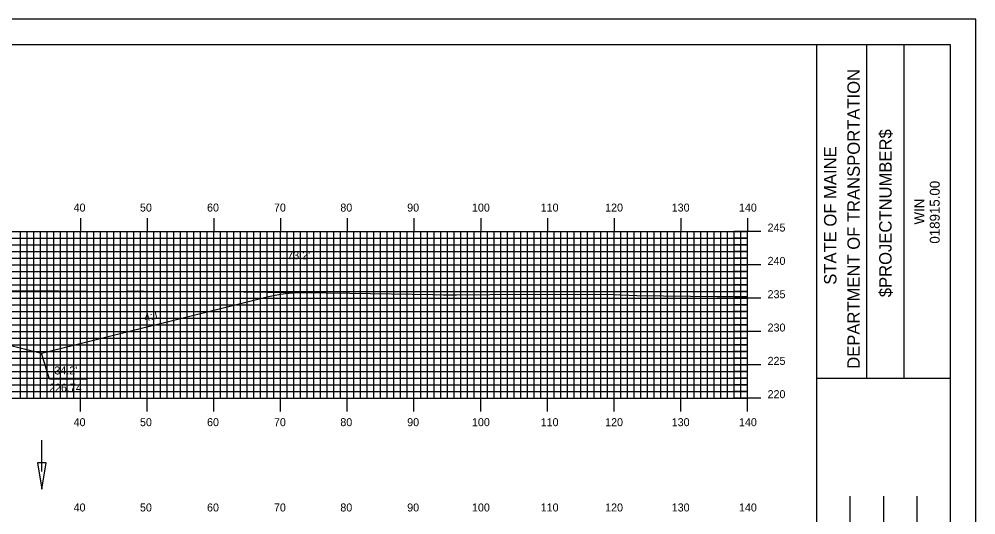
# Model space of a CAD drawing. Extents: x 1802716 to 1803060, y 442591 to 442811.
# Drawn here: x 1802912.9 to 1803056.3, y 442736.2 to 442810.5 of the extents above; entities that cross this region are included whole.
import ezdxf

# ---------------------------------------------------------------- set-up
doc = ezdxf.new("R2010")
doc.units = 0
for name, color, linetype in [('ANNOTATION', 7, 'Continuous'), ('BORDER', 7, 'Continuous'), ('D_Drainage_Ditch_Line', 7, 'Continuous'), ('D_Roadway_Centerline', 7, 'Continuous'), ('D_Roadway_SlopeLines', 7, 'Continuous'), ('D_Text_Standard', 7, 'Continuous'), ('H_V ANNOTATION', 7, 'Continuous'), ('MAJOR', 7, 'Continuous'), ('MINOR', 7, 'Continuous'), ('PLOT BOUNDARY', 7, 'Continuous'), ('S_Roadway_Centerline', 7, 'Continuous')]:
    doc.layers.add(name, color=color, linetype=linetype)

msp = doc.modelspace()

# ---------------------------------------------------------------- linework, layer by layer
at = {"layer": 'ANNOTATION'}
msp.add_lwpolyline([(1802923.17, 442756.5), (1802917.48, 442756.5), (1802916.29, 442760.41)], dxfattribs=at)
at = {"layer": 'BORDER'}
for p, q in [((1803032.51, 442596.67), (1803032.51, 442806.67)), ((1803039.97, 442756.66), (1803039.97, 442806.66)), ((1803045.56, 442756.66), (1803045.56, 442806.66)), ((1803032.52, 442756.65), (1803052.51, 442756.65)), ((1803037.51, 442721.67), (1803037.51, 442738.97)), ((1803042.51, 442721.67), (1803042.51, 442738.97)), ((1803047.51, 442721.67), (1803047.51, 442738.97))]:
    msp.add_line(p, q, dxfattribs=at)
msp.add_lwpolyline([(1802732.51, 442596.67), (1803052.51, 442596.67), (1803052.51, 442806.67), (1802732.51, 442806.67)], close=True, dxfattribs=at)
at = {"layer": 'D_Drainage_Ditch_Line'}
msp.add_line((1802916.32, 442742.65), (1802916.32, 442747.35), dxfattribs=at)
msp.add_lwpolyline([(1802916.97, 442743.96), (1802915.66, 442743.96), (1802916.32, 442740.03)], close=True, dxfattribs=at)
at = {"layer": 'D_Roadway_Centerline'}
msp.add_lwpolyline([(1802805.64, 442770.35), (1802806.89, 442770.32), (1802808.14, 442770.2), (1802809.39, 442770.01), (1802810.64, 442769.74), (1802847.94, 442760.41), (1802851.94, 442761.41), (1802862.11, 442763.95), (1802870.11, 442764.27), (1802882.11, 442764.51), (1802894.11, 442764.27), (1802902.11, 442763.95), (1802912.29, 442761.41), (1802916.29, 442760.41), (1802950.28, 442768.91), (1802951.53, 442769.18), (1802952.78, 442769.37), (1802954.03, 442769.48), (1802955.28, 442769.51)], dxfattribs=at)
at = {"layer": 'D_Roadway_SlopeLines'}
for points in [[(1802916.29, 442760.41), (1802950.28, 442768.91), (1802951.53, 442769.18), (1802952.78, 442769.37), (1802954.03, 442769.48), (1802955.28, 442769.51)], [(1802902.11, 442763.95), (1802916.29, 442760.41)]]:
    msp.add_lwpolyline(points, dxfattribs=at)
at = {"layer": 'MAJOR'}
for p, q in [((1802922.11, 442780.67), (1802922.11, 442778.67)), ((1802932.11, 442780.67), (1802932.11, 442778.67)), ((1802942.11, 442780.67), (1802942.11, 442778.67)), ((1802952.11, 442780.67), (1802952.11, 442778.67)), ((1802962.11, 442780.67), (1802962.11, 442778.67)), ((1802972.11, 442780.67), (1802972.11, 442778.67)), ((1802982.11, 442780.67), (1802982.11, 442778.67)), ((1802992.11, 442780.67), (1802992.11, 442778.67)), ((1803002.11, 442780.67), (1803002.11, 442778.67)), ((1803012.11, 442780.67), (1803012.11, 442778.67)), ((1803022.11, 442780.67), (1803022.11, 442778.67)), ((1802742.11, 442778.67), (1803022.11, 442778.67)), ((1802742.11, 442778.67), (1803022.11, 442778.67)), ((1802922.11, 442753.67), (1802922.11, 442778.67)), ((1802932.11, 442753.67), (1802932.11, 442778.67)), ((1802942.11, 442753.67), (1802942.11, 442778.67)), ((1802952.11, 442753.67), (1802952.11, 442778.67)), ((1802962.11, 442753.67), (1802962.11, 442778.67)), ((1802972.11, 442753.67), (1802972.11, 442778.67)), ((1802982.11, 442753.67), (1802982.11, 442778.67)), ((1802992.11, 442753.67), (1802992.11, 442778.67)), ((1803002.11, 442753.67), (1803002.11, 442778.67)), ((1803012.11, 442753.67), (1803012.11, 442778.67)), ((1803024.12, 442778.67), (1803020.11, 442778.67)), ((1803022.11, 442753.67), (1803022.11, 442778.67)), ((1803022.11, 442753.67), (1803022.11, 442778.67)), ((1802742.11, 442773.67), (1803022.11, 442773.67)), ((1803024.12, 442773.67), (1803020.11, 442773.67)), ((1802742.11, 442768.67), (1803022.11, 442768.67)), ((1803024.12, 442768.67), (1803020.11, 442768.67)), ((1802742.11, 442763.67), (1803022.11, 442763.67)), ((1803024.12, 442763.67), (1803020.11, 442763.67)), ((1802742.11, 442758.67), (1803022.11, 442758.67)), ((1803024.12, 442758.67), (1803020.11, 442758.67)), ((1802742.11, 442753.67), (1803022.11, 442753.67)), ((1802742.11, 442753.67), (1803022.11, 442753.67)), ((1802922.11, 442751.66), (1802922.11, 442753.67)), ((1802932.11, 442751.66), (1802932.11, 442753.67)), ((1802942.11, 442751.66), (1802942.11, 442753.67)), ((1802952.11, 442751.66), (1802952.11, 442753.67)), ((1802962.11, 442751.66), (1802962.11, 442753.67)), ((1802972.11, 442751.66), (1802972.11, 442753.67)), ((1802982.11, 442751.66), (1802982.11, 442753.67)), ((1802992.11, 442751.66), (1802992.11, 442753.67)), ((1803002.11, 442751.66), (1803002.11, 442753.67)), ((1803012.11, 442751.66), (1803012.11, 442753.67)), ((1803024.12, 442753.67), (1803020.11, 442753.67)), ((1803022.11, 442751.66), (1803022.11, 442753.67))]:
    msp.add_line(p, q, dxfattribs=at)
at = {"layer": 'MINOR'}
for p, q in [((1802913.11, 442753.67), (1802913.11, 442778.67)), ((1802914.11, 442753.67), (1802914.11, 442778.67)), ((1802915.11, 442753.67), (1802915.11, 442778.67)), ((1802916.11, 442753.67), (1802916.11, 442778.67)), ((1802917.11, 442753.67), (1802917.11, 442778.67)), ((1802918.11, 442753.67), (1802918.11, 442778.67)), ((1802919.11, 442753.67), (1802919.11, 442778.67)), ((1802920.11, 442753.67), (1802920.11, 442778.67)), ((1802921.11, 442753.67), (1802921.11, 442778.67)), ((1802923.11, 442753.67), (1802923.11, 442778.67)), ((1802924.11, 442753.67), (1802924.11, 442778.67)), ((1802925.11, 442753.67), (1802925.11, 442778.67)), ((1802926.11, 442753.67), (1802926.11, 442778.67)), ((1802927.11, 442753.67), (1802927.11, 442778.67)), ((1802928.11, 442753.67), (1802928.11, 442778.67)), ((1802929.11, 442753.67), (1802929.11, 442778.67)), ((1802930.11, 442753.67), (1802930.11, 442778.67)), ((1802931.11, 442753.67), (1802931.11, 442778.67)), ((1802933.11, 442753.67), (1802933.11, 442778.67)), ((1802934.11, 442753.67), (1802934.11, 442778.67)), ((1802935.11, 442753.67), (1802935.11, 442778.67)), ((1802936.11, 442753.67), (1802936.11, 442778.67)), ((1802937.11, 442753.67), (1802937.11, 442778.67)), ((1802938.11, 442753.67), (1802938.11, 442778.67)), ((1802939.11, 442753.67), (1802939.11, 442778.67)), ((1802940.11, 442753.67), (1802940.11, 442778.67)), ((1802941.11, 442753.67), (1802941.11, 442778.67)), ((1802943.11, 442753.67), (1802943.11, 442778.67)), ((1802944.11, 442753.67), (1802944.11, 442778.67)), ((1802945.11, 442753.67), (1802945.11, 442778.67)), ((1802946.11, 442753.67), (1802946.11, 442778.67)), ((1802947.11, 442753.67), (1802947.11, 442778.67)), ((1802948.11, 442753.67), (1802948.11, 442778.67)), ((1802949.11, 442753.67), (1802949.11, 442778.67)), ((1802950.11, 442753.67), (1802950.11, 442778.67)), ((1802951.11, 442753.67), (1802951.11, 442778.67)), ((1802953.11, 442753.67), (1802953.11, 442778.67)), ((1802954.11, 442753.67), (1802954.11, 442778.67)), ((1802955.11, 442753.67), (1802955.11, 442778.67)), ((1802956.11, 442753.67), (1802956.11, 442778.67)), ((1802957.11, 442753.67), (1802957.11, 442778.67)), ((1802958.11, 442753.67), (1802958.11, 442778.67)), ((1802959.11, 442753.67), (1802959.11, 442778.67)), ((1802960.11, 442753.67), (1802960.11, 442778.67)), ((1802961.11, 442753.67), (1802961.11, 442778.67)), ((1802963.11, 442753.67), (1802963.11, 442778.67)), ((1802964.11, 442753.67), (1802964.11, 442778.67)), ((1802965.11, 442753.67), (1802965.11, 442778.67)), ((1802966.11, 442753.67), (1802966.11, 442778.67)), ((1802967.11, 442753.67), (1802967.11, 442778.67)), ((1802968.11, 442753.67), (1802968.11, 442778.67)), ((1802969.11, 442753.67), (1802969.11, 442778.67)), ((1802970.11, 442753.67), (1802970.11, 442778.67)), ((1802971.11, 442753.67), (1802971.11, 442778.67)), ((1802973.11, 442753.67), (1802973.11, 442778.67)), ((1802974.11, 442753.67), (1802974.11, 442778.67)), ((1802975.11, 442753.67), (1802975.11, 442778.67)), ((1802976.11, 442753.67), (1802976.11, 442778.67)), ((1802977.11, 442753.67), (1802977.11, 442778.67)), ((1802978.11, 442753.67), (1802978.11, 442778.67)), ((1802979.11, 442753.67), (1802979.11, 442778.67)), ((1802980.11, 442753.67), (1802980.11, 442778.67)), ((1802981.11, 442753.67), (1802981.11, 442778.67)), ((1802983.11, 442753.67), (1802983.11, 442778.67)), ((1802984.11, 442753.67), (1802984.11, 442778.67)), ((1802985.11, 442753.67), (1802985.11, 442778.67)), ((1802986.11, 442753.67), (1802986.11, 442778.67)), ((1802987.11, 442753.67), (1802987.11, 442778.67)), ((1802988.11, 442753.67), (1802988.11, 442778.67)), ((1802989.11, 442753.67), (1802989.11, 442778.67)), ((1802990.11, 442753.67), (1802990.11, 442778.67)), ((1802991.11, 442753.67), (1802991.11, 442778.67)), ((1802993.11, 442753.67), (1802993.11, 442778.67)), ((1802994.11, 442753.67), (1802994.11, 442778.67)), ((1802995.11, 442753.67), (1802995.11, 442778.67)), ((1802996.11, 442753.67), (1802996.11, 442778.67)), ((1802997.11, 442753.67), (1802997.11, 442778.67)), ((1802998.11, 442753.67), (1802998.11, 442778.67)), ((1802999.11, 442753.67), (1802999.11, 442778.67)), ((1803000.11, 442753.67), (1803000.11, 442778.67)), ((1803001.11, 442753.67), (1803001.11, 442778.67)), ((1803003.11, 442753.67), (1803003.11, 442778.67)), ((1803004.11, 442753.67), (1803004.11, 442778.67)), ((1803005.11, 442753.67), (1803005.11, 442778.67)), ((1803006.11, 442753.67), (1803006.11, 442778.67)), ((1803007.11, 442753.67), (1803007.11, 442778.67)), ((1803008.11, 442753.67), (1803008.11, 442778.67)), ((1803009.11, 442753.67), (1803009.11, 442778.67)), ((1803010.11, 442753.67), (1803010.11, 442778.67)), ((1803011.11, 442753.67), (1803011.11, 442778.67)), ((1803013.11, 442753.67), (1803013.11, 442778.67)), ((1803014.11, 442753.67), (1803014.11, 442778.67)), ((1803015.11, 442753.67), (1803015.11, 442778.67)), ((1803016.11, 442753.67), (1803016.11, 442778.67)), ((1803017.11, 442753.67), (1803017.11, 442778.67)), ((1803018.11, 442753.67), (1803018.11, 442778.67)), ((1803019.11, 442753.67), (1803019.11, 442778.67)), ((1803020.11, 442753.67), (1803020.11, 442778.67)), ((1803021.11, 442753.67), (1803021.11, 442778.67)), ((1802742.11, 442777.67), (1803022.11, 442777.67)), ((1803022.11, 442777.67), (1803020.11, 442777.67)), ((1802742.11, 442776.67), (1803022.11, 442776.67)), ((1802742.11, 442775.67), (1803022.11, 442775.67)), ((1803022.11, 442776.67), (1803020.11, 442776.67)), ((1803022.11, 442775.67), (1803020.11, 442775.67)), ((1802742.11, 442774.67), (1803022.11, 442774.67)), ((1803022.11, 442774.67), (1803020.11, 442774.67)), ((1802742.11, 442772.67), (1803022.11, 442772.67)), ((1802742.11, 442771.67), (1803022.11, 442771.67)), ((1803022.11, 442772.67), (1803020.11, 442772.67)), ((1803022.11, 442771.67), (1803020.11, 442771.67)), ((1802742.11, 442770.67), (1803022.11, 442770.67)), ((1803022.11, 442770.67), (1803020.11, 442770.67)), ((1802742.11, 442769.67), (1803022.11, 442769.67)), ((1803022.11, 442769.67), (1803020.11, 442769.67)), ((1802742.11, 442767.67), (1803022.11, 442767.67)), ((1803022.11, 442767.67), (1803020.11, 442767.67)), ((1802742.11, 442766.67), (1803022.11, 442766.67)), ((1802742.11, 442765.67), (1803022.11, 442765.67)), ((1803022.11, 442766.67), (1803020.11, 442766.67)), ((1803022.11, 442765.67), (1803020.11, 442765.67)), ((1802742.11, 442764.67), (1803022.11, 442764.67)), ((1803022.11, 442764.67), (1803020.11, 442764.67)), ((1802742.11, 442762.67), (1803022.11, 442762.67)), ((1802742.11, 442761.67), (1803022.11, 442761.67)), ((1803022.11, 442762.67), (1803020.11, 442762.67)), ((1803022.11, 442761.67), (1803020.11, 442761.67)), ((1802742.11, 442760.67), (1803022.11, 442760.67)), ((1803022.11, 442760.67), (1803020.11, 442760.67)), ((1802742.11, 442759.67), (1803022.11, 442759.67)), ((1803022.11, 442759.67), (1803020.11, 442759.67)), ((1802742.11, 442757.67), (1803022.11, 442757.67)), ((1803022.11, 442757.67), (1803020.11, 442757.67)), ((1802742.11, 442756.67), (1803022.11, 442756.67)), ((1802742.11, 442755.67), (1803022.11, 442755.67)), ((1803022.11, 442756.67), (1803020.11, 442756.67)), ((1803022.11, 442755.67), (1803020.11, 442755.67)), ((1802742.11, 442754.67), (1803022.11, 442754.67)), ((1803022.11, 442754.67), (1803020.11, 442754.67))]:
    msp.add_line(p, q, dxfattribs=at)
at = {"layer": 'PLOT BOUNDARY'}
msp.add_lwpolyline([(1802716.33, 442590.55), (1803056.33, 442590.55), (1803056.33, 442810.55), (1802716.33, 442810.55)], close=True, dxfattribs=at)
at = {"layer": 'S_Roadway_Centerline'}
msp.add_lwpolyline([(1802910.69, 442769.77), (1802918.81, 442769.76), (1802927.41, 442769.7), (1802930.66, 442769.76), (1802933.61, 442769.61), (1802943.05, 442769.67), (1802953.65, 442769.52), (1802955.36, 442769.51), (1802962.48, 442769.41), (1802974.94, 442769.22), (1802976.46, 442769.16), (1802978.49, 442769.19), (1802988.53, 442769.28), (1802996.66, 442769.22), (1803000.81, 442769.27), (1803005.49, 442769.06), (1803017.53, 442768.93), (1803022.11, 442768.95)], dxfattribs=at)

# ---------------------------------------------------------------- texts
at = {"layer": 'ANNOTATION'}
msp.add_text('4:1', height=1.2, rotation=14.0362, dxfattribs=at).set_placement((1802931.82, 442765.15))
for s, p in [("34.2'", (1802918.21, 442757.23)), ('226.74', (1802917.41, 442754.63))]:
    msp.add_text(s, height=1.2, dxfattribs=at).set_placement(p)
at = {"layer": 'BORDER'}
for s, height, p in [('DEPARTMENT OF TRANSPORTATION', 1.8635, (1803038.93, 442758.08)), ('$PROJECTNUMBER$', 1.8635, (1803043.7, 442768.82)), ('STATE OF MAINE', 1.8635, (1803035.43, 442770.69)), ('018915.00', 1.491, (1803050.91, 442776.86)), ('WIN', 1.491, (1803048.59, 442779.73))]:
    msp.add_text(s, height=height, rotation=90, dxfattribs=at).set_placement(p)
at = {"layer": 'D_Text_Standard'}
msp.add_text("73.2'", height=1.2, dxfattribs=at).set_placement((1802953.12, 442774.52))
at = {"layer": 'H_V ANNOTATION'}
for s, p in [('40', (1802921.09, 442781.67)), ('50', (1802931.04, 442781.67)), ('60', (1802941.09, 442781.67)), ('70', (1802951.12, 442781.67)), ('80', (1802961.07, 442781.67)), ('90', (1802971.09, 442781.67)), ('100', (1802980.8, 442781.67)), ('110', (1802991.1, 442781.67)), ('120', (1803000.76, 442781.67)), ('130', (1803010.74, 442781.67)), ('140', (1803020.82, 442781.67)), ('245', (1803025.11, 442778.67)), ('240', (1803025.11, 442773.67)), ('235', (1803025.11, 442768.67)), ('230', (1803025.11, 442763.67)), ('225', (1803025.11, 442758.67)), ('220', (1803025.11, 442753.67)), ('40', (1802921.09, 442749.47)), ('50', (1802931.04, 442749.47)), ('60', (1802941.09, 442749.47)), ('70', (1802951.12, 442749.47)), ('80', (1802961.07, 442749.47)), ('90', (1802971.09, 442749.47)), ('100', (1802980.8, 442749.47)), ('110', (1802991.1, 442749.47)), ('120', (1803000.76, 442749.47)), ('130', (1803010.74, 442749.47)), ('140', (1803020.82, 442749.47)), ('40', (1802921.09, 442736.67)), ('50', (1802931.04, 442736.67)), ('60', (1802941.09, 442736.67)), ('70', (1802951.12, 442736.67)), ('80', (1802961.07, 442736.67)), ('90', (1802971.09, 442736.67)), ('100', (1802980.8, 442736.67)), ('110', (1802991.1, 442736.67)), ('120', (1803000.76, 442736.67)), ('130', (1803010.74, 442736.67)), ('140', (1803020.82, 442736.67))]:
    msp.add_text(s, height=1.2, dxfattribs=at).set_placement(p)

doc.saveas('drawing.dxf')
